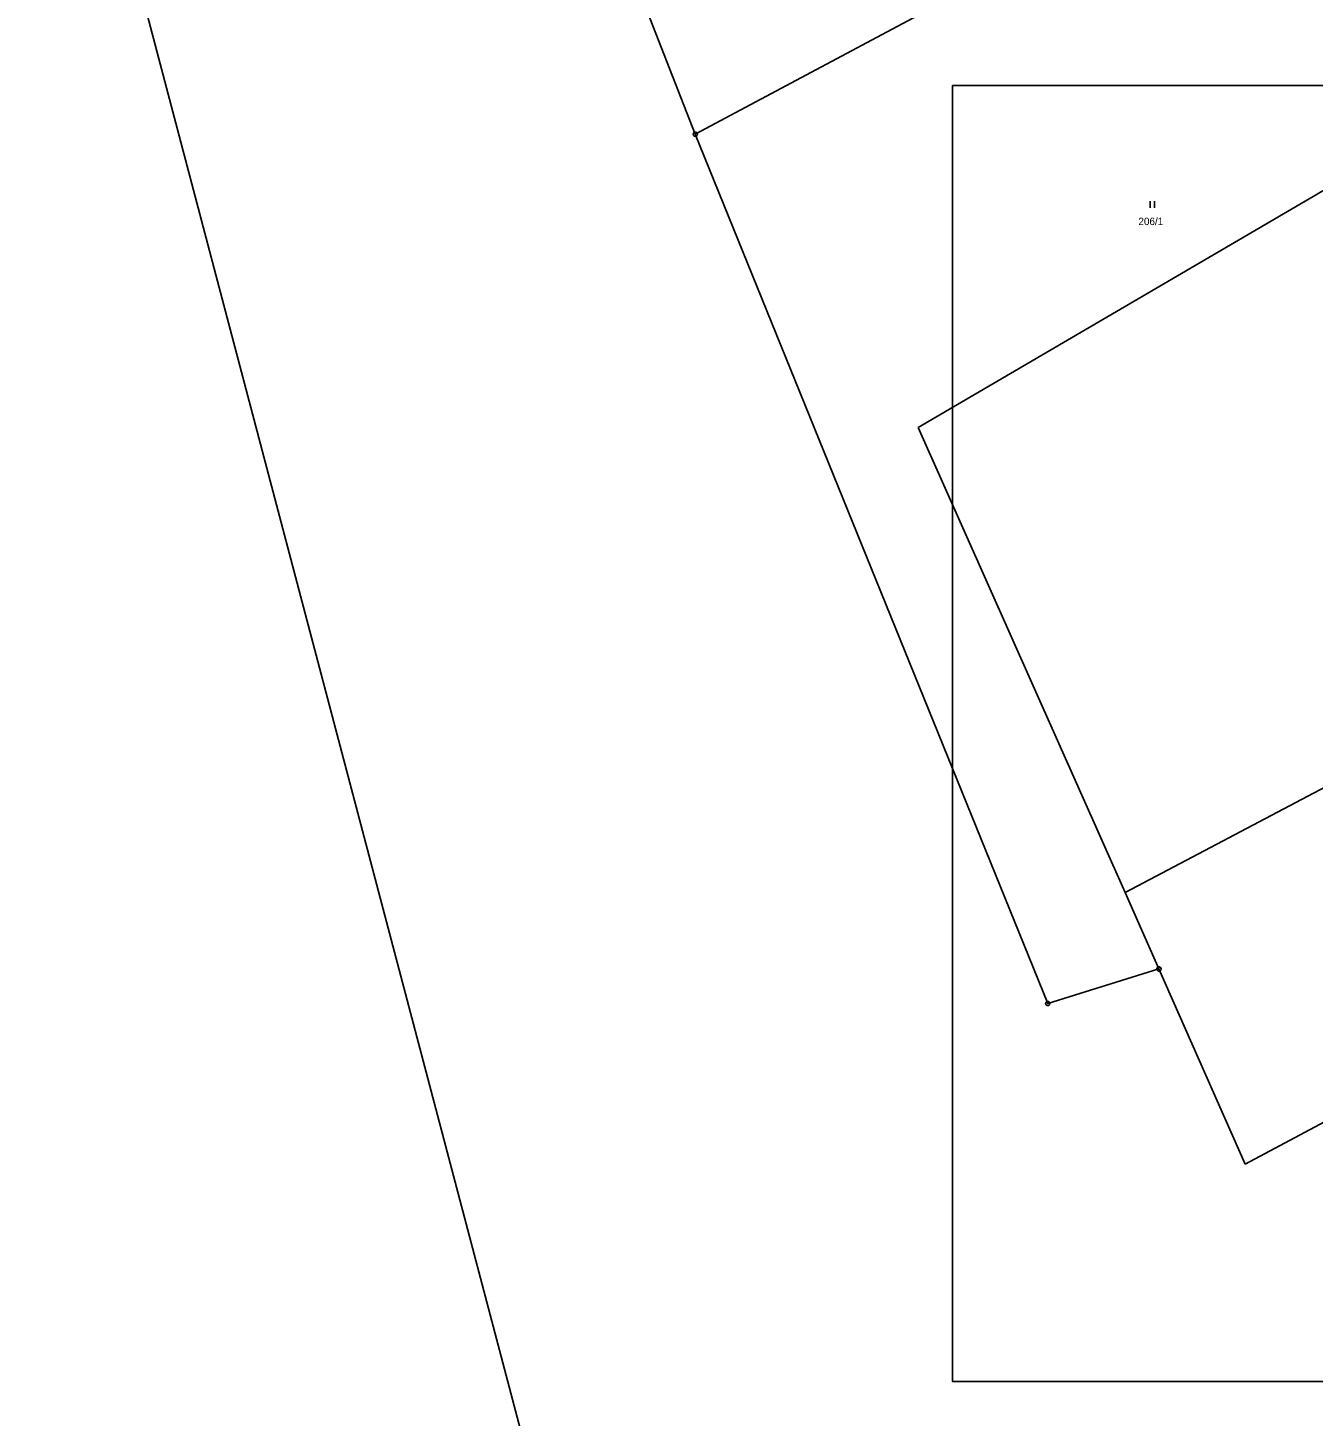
# Model space of a CAD drawing. Extents: x -871430 to -870620, y -1010094 to -1009649.
# Drawn here: x -871112 to -871038.3, y -1009984.7 to -1009905.2 of the extents above; entities that cross this region are included whole.
import ezdxf

# ---------------------------------------------------------------- set-up
doc = ezdxf.new("R2010")
doc.units = 0
for name, color, linetype in [('Vrstva 1', 7, 'Continuous'), ('Vrstva 2', 7, 'Continuous'), ('Vrstva 3', 7, 'Continuous'), ('Vrstva 63', 7, 'Continuous'), ('Vrstva 8', 7, 'Continuous')]:
    doc.layers.add(name, color=color, linetype=linetype)

msp = doc.modelspace()

# ---------------------------------------------------------------- linework, layer by layer
at = {"layer": 'Vrstva 1'}
for p, q in [((-871088.8, -1009872.78), (-871073.74, -1009911.25)), ((-871111.98, -1009878.48), (-871077.55, -1010009.01)), ((-871073.74, -1009911.25), (-871032.87, -1009889.43)), ((-871024.02, -1009906.43), (-871060.98, -1009928.05)), ((-871073.74, -1009911.25), (-871053.55, -1009961.06)), ((-871060.98, -1009928.05), (-871049.12, -1009954.69)), ((-871007.7, -1009932.83), (-871049.12, -1009954.69)), ((-871042.24, -1009970.27), (-871000.21, -1009947.8)), ((-871049.12, -1009954.69), (-871047.18, -1009959.08)), ((-871053.55, -1009961.06), (-871047.18, -1009959.08)), ((-871047.18, -1009959.08), (-871042.24, -1009970.27))]:
    msp.add_line(p, q, dxfattribs=at)
at = {"layer": 'Vrstva 3'}
for p, q in [((-871047.691, -1009915.09), (-871047.691, -1009915.465)), ((-871047.441, -1009915.465), (-871047.441, -1009915.09))]:
    msp.add_line(p, q, dxfattribs=at)
at = {"layer": 'Vrstva 63'}
msp.add_lwpolyline([(-871059.002, -1009908.468), (-870954.002, -1009908.468), (-870954.002, -1009982.718), (-871059.002, -1009982.718), (-871059.002, -1009908.468)], dxfattribs=at)
at = {"layer": 'Vrstva 8'}
for p, q in [((-871073.752, -1009911.25), (-871073.728, -1009911.25)), ((-871047.192, -1009959.08), (-871047.168, -1009959.08)), ((-871053.562, -1009961.06), (-871053.538, -1009961.06))]:
    msp.add_line(p, q, dxfattribs=at)
for points in [[(-871073.702, -1009911.13), (-871073.64, -1009911.178), (-871073.615, -1009911.25), (-871073.64, -1009911.322), (-871073.702, -1009911.37), (-871073.778, -1009911.37), (-871073.84, -1009911.322), (-871073.865, -1009911.25), (-871073.84, -1009911.178), (-871073.778, -1009911.13), (-871073.702, -1009911.13)], [(-871047.143, -1009958.96), (-871047.08, -1009959.008), (-871047.055, -1009959.08), (-871047.08, -1009959.152), (-871047.143, -1009959.2), (-871047.218, -1009959.2), (-871047.28, -1009959.152), (-871047.305, -1009959.08), (-871047.28, -1009959.008), (-871047.218, -1009958.96), (-871047.143, -1009958.96)], [(-871053.513, -1009960.94), (-871053.45, -1009960.988), (-871053.425, -1009961.06), (-871053.45, -1009961.133), (-871053.513, -1009961.18), (-871053.588, -1009961.18), (-871053.65, -1009961.133), (-871053.675, -1009961.06), (-871053.65, -1009960.988), (-871053.588, -1009960.94), (-871053.513, -1009960.94)]]:
    msp.add_lwpolyline(points, dxfattribs=at)

# ---------------------------------------------------------------- texts
at = {"layer": 'Vrstva 2'}
msp.add_text('206/1', height=0.425, dxfattribs=at).set_placement((-871048.356, -1009916.459))

doc.saveas('drawing.dxf')
